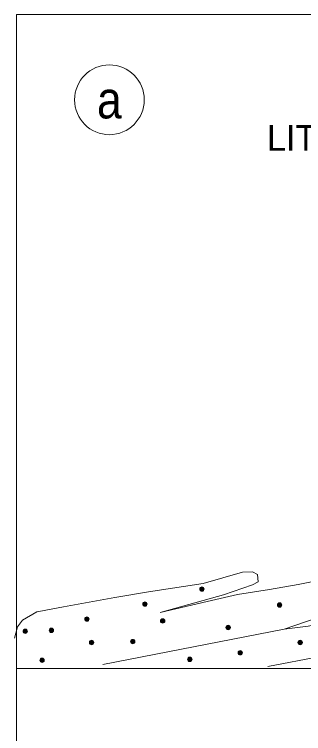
# Model space of a CAD drawing. Extents: x -175 to 1110, y -14 to 1804.
# Drawn here: x 196.2 to 308.3, y 1160.1 to 1438.4 of the extents above; entities that cross this region are included whole.
import ezdxf
from ezdxf.enums import TextEntityAlignment as Align

# ---------------------------------------------------------------- set-up
doc = ezdxf.new("R2010")
doc.units = 0
doc.header["$LTSCALE"] = 4
doc.layers.add('1', color=7, linetype='Continuous', lineweight=13)
doc.layers.add('12', color=7, linetype='Continuous', lineweight=13)

msp = doc.modelspace()

# ---------------------------------------------------------------- hatches: boundary and pattern name
at = {"layer": '12'}
for points in [[(269.759, 1216.029, 1), (268.054, 1216.029, 1)], [(247.648, 1210.233, 1), (245.943, 1210.233, 1)], [(299.848, 1209.873, 1), (298.143, 1209.873, 1)], [(225.177, 1204.43, 1), (223.472, 1204.43, 1)], [(254.538, 1203.71, 1), (252.833, 1203.71, 1)], [(201.251, 1199.721, 1), (199.546, 1199.721, 1)], [(211.403, 1200.081, 1), (209.698, 1200.081, 1)], [(279.911, 1201.169, 1), (278.206, 1201.169, 1)], [(226.984, 1195.373, 1), (225.279, 1195.373, 1)], [(242.939, 1195.733, 1), (241.234, 1195.733, 1)], [(307.826, 1195.373, 1), (306.121, 1195.373, 1)], [(284.62, 1191.384, 1), (282.915, 1191.384, 1)], [(207.774, 1188.482, 1), (206.069, 1188.482, 1)], [(265.05, 1188.849, 1), (263.345, 1188.849, 1)]]:
    msp.add_hatch(color=256, dxfattribs=at).paths.add_polyline_path(points)

# ---------------------------------------------------------------- linework, layer by layer
at = {"layer": '1'}
for p, q in [((300.78, 1200.48), (230.49, 1186.89)), ((197.04, 1185.78), (197.04, 1197.09)), ((353.58, 1197.41), (294.48, 1186.14)), ((414.39, 1185.26), (197.04, 1185.26)), ((197.04, 1185.26), (732.24, 1185.26))]:
    msp.add_line(p, q, dxfattribs=at)
msp.add_lwpolyline([(197.04, 517.8), (732.71, 517.8), (732.71, 1438.42), (197.04, 1438.42)], close=True, dxfattribs=at)
for points in [[(413.59, 1227.79), (394.65, 1222.85), (376.28, 1217.16), (361.03, 1213.09), (350, 1210.45), (334.02, 1206.76), (325.94, 1205.74), (316.75, 1203.08), (310.14, 1201.68), (300.78, 1200.48), (325.61, 1209.03), (348.19, 1213.22), (362.34, 1217.66), (377.05, 1221.55), (388.26, 1225.11), (399.12, 1229.58), (407.95, 1234.26), (412.01, 1237.51), (414.97, 1240.78)], [(204.9, 1207.22), (205.73, 1207.36), (215.28, 1209.12), (235.15, 1212.81), (248.21, 1214.92), (269.34, 1218.24), (284.61, 1222.52), (288.47, 1222.67), (290.49, 1221.74), (290.65, 1218.82), (288.44, 1217.73), (277.2, 1213.78), (252.73, 1207.01), (270.94, 1211.26), (282.71, 1213.92), (295.03, 1215.84), (306.25, 1217.77), (327.22, 1222.02)], [(196.19, 1197.09), (197.45, 1201.49), (199.33, 1204), (204.9, 1207.22)]]:
    msp.add_lwpolyline(points, dxfattribs=at)
msp.add_circle((233.041, 1405.367), 13.5, dxfattribs=at)
at = {"layer": '12'}
for centre in [(268.907, 1216.029), (246.796, 1210.233), (298.996, 1209.873), (224.324, 1204.43), (253.686, 1203.71), (200.399, 1199.721), (210.551, 1200.081), (279.059, 1201.169), (226.132, 1195.373), (242.087, 1195.733), (306.973, 1195.373), (283.768, 1191.384), (206.922, 1188.482), (264.198, 1188.849)]:
    msp.add_circle(centre, 0.853, dxfattribs=at)

# ---------------------------------------------------------------- texts
at = {"layer": '1', "width": 0.9}
msp.add_text('a', height=14.4, dxfattribs=at).set_placement((233.03, 1398.17), align=Align.CENTER)
at = {"layer": '1'}
msp.add_text('LITORÂNEA', height=9.9, dxfattribs=at).set_placement((294.11, 1385.66))

doc.saveas('drawing.dxf')
